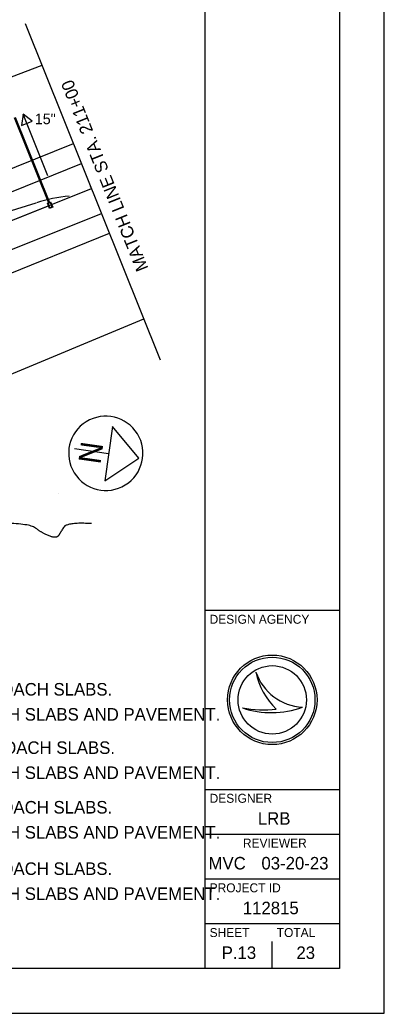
# Model space of a CAD drawing. Extents: x 0 to 3400, y 0 to 2200.
# Drawn here: x 2993 to 3400, y 0 to 1110 of the extents above; entities that cross this region are included whole.
import ezdxf

# ---------------------------------------------------------------- set-up
doc = ezdxf.new("R2010")
doc.units = 0
for name, color, linetype in [('Default', 7, 'Continuous'), ('DR_X_Culvert', 7, 'Continuous'), ('DR_X_Text', 7, 'Continuous'), ('HY_X_Water_Edge', 7, 'Continuous'), ('PV_P_EOP', 7, 'Continuous'), ('RD_X_GR_Rt', 7, 'Continuous'), ('RW_X_Esmt_LA', 7, 'Continuous'), ('SH_Border', 7, 'Continuous'), ('SH_Cut_Line', 7, 'Continuous'), ('SH_Data', 7, 'Continuous')]:
    doc.layers.add(name, color=color, linetype=linetype)

msp = doc.modelspace()

# ---------------------------------------------------------------- linework, layer by layer
at = {"layer": 'Default'}
for p, q in [((2516.4, 697.6), (3073.1, 921.3)), ((3073.1, 921.3), (3072, 924))]:
    msp.add_line(p, q, dxfattribs=at)
for points in [[(3068.5, 919.4), (3073.1, 921.3)], [(2989.6, 887.7), (3063.8, 917.5)]]:
    msp.add_lwpolyline(points, dxfattribs=at)
at = {"layer": 'DR_X_Culvert'}
for p, q in [((3025.2, 904.7), (2986.9, 1000.1)), ((3026.4, 905.2), (2988, 1000.6)), ((3024.5, 904.5), (3027, 905.5)), ((3026.4, 899.8), (3024.5, 904.5)), ((3028.9, 900.8), (3026.4, 899.8)), ((3026.7, 902.6), (3026.7, 902.6)), ((3027, 905.5), (3028.9, 900.8))]:
    msp.add_line(p, q, dxfattribs=at)
msp.add_lwpolyline([(3029.8, 900.4), (3026.1, 898.9), (3023.7, 904.8), (3027.4, 906.3)], close=True, dxfattribs=at)
at = {"layer": 'DR_X_Text'}
for p, q in [((2996.7, 1004.2), (2994.9, 991.6)), ((3006.7, 996.4), (2996.7, 1004.2)), ((3024.4, 935.3), (2996.7, 1004.2)), ((2994.9, 991.8), (3006.7, 996.4))]:
    msp.add_line(p, q, dxfattribs=at)
at = {"layer": 'HY_X_Water_Edge'}
msp.add_open_spline([(3073.2, 546.9), (3045, 548.5), (3038.4, 536.6), (3033.6, 529.9), (3016.3, 537.1), (3006, 546), (2961, 548.1), (2949.8, 543.4), (2942.1, 532.9), (2929.7, 537.6), (2916.8, 538.2), (2902.2, 537.1), (2870.7, 541.7), (2847, 544), (2823.9, 549.5), (2805.1, 567.2), (2793.2, 584.8), (2776.5, 595.7), (2754, 599.6), (2729.9, 599), (2714, 591.1), (2690.6, 580.9), (2666.4, 566.4), (2657.9, 560.2), (2647.7, 559.9), (2638.2, 556.9), (2609.5, 534.6), (2600.4, 523.1), (2582.7, 509.5), (2561.3, 498.8), (2543.4, 486.2)], degree=2, dxfattribs=at)
at = {"layer": 'PV_P_EOP'}
for p, q in [((2787.8, 864.8), (3053, 971.4)), ((2796.8, 842.6), (3061.9, 949.1)), ((2819.2, 786.9), (3084.3, 893.4)), ((2828.1, 764.6), (3093.3, 871.2))]:
    msp.add_line(p, q, dxfattribs=at)
at = {"layer": 'RD_X_GR_Rt'}
msp.add_line((2832.3, 850), (3011.4, 905.4), dxfattribs=at)
msp.add_arc((3060.2, 754.6), 158.5, 94.3743, 107.9297, dxfattribs=at)
at = {"layer": 'RW_X_Esmt_LA'}
for p, q in [((2751.3, 957.9), (3017.8, 1058.9)), ((2947, 698.7), (3131.6, 775.7))]:
    msp.add_line(p, q, dxfattribs=at)
at = {"layer": 'SH_Border'}
for p, q in [((3200, 50), (3200, 2150)), ((3200, 450), (3350, 450)), ((3200, 250), (3350, 250)), ((3200, 200), (3350, 200)), ((3200, 150), (3350, 150)), ((3200, 100), (3350, 100))]:
    msp.add_line(p, q, dxfattribs=at)
msp.add_lwpolyline([(150, 2150), (3350, 2150), (3350, 50), (150, 50)], close=True, dxfattribs=at)
at = {"layer": 'SH_Cut_Line'}
msp.add_line((3073.1, 921.3), (3073.1, 921.3), dxfattribs=at)
msp.add_lwpolyline([(0, 0), (3400, 0), (3400, 2200), (0, 2200)], close=True, dxfattribs=at)
at = {"layer": 'SH_Data'}
for p, q in [((3150.2, 729.3), (2999.2, 1105.3)), ((3096.5, 655.4), (3087.9, 594.5)), ((3126, 620.1), (3096.5, 655.4)), ((3092.2, 624.9), (3053.9, 630.4)), ((3087.9, 594.5), (3126, 620.1)), ((3036.7, 580.9), (3036.7, 580.9)), ((3256.7, 381), (3256.7, 381)), ((3275, 350), (3275, 350)), ((3241.7, 341), (3241.7, 341)), ((3308.7, 341.9), (3308.7, 341.9)), ((3275, 50), (3275, 80)), ((3237.5, 67.5), (3237.5, 67.5))]:
    msp.add_line(p, q, dxfattribs=at)
for radius in [50, 47.7, 47.7, 38.2]:
    msp.add_circle((3275, 350), radius, dxfattribs=at)
for centre, radius, start, end in [((3089, 625.4), 41.5, 31.6982, 31.6817), ((3311.6, 399.8), 58, 198.9257, 198.9319), ((3334.7, 397), 79.6, 191.6379, 191.6421), ((3311.6, 399.8), 58, 198.9319, 267.1657), ((3334.7, 397), 79.6, 191.6421, 226.0947), ((3273.9, 437), 101.3, 251.4576, 290.0832), ((3264.8, 465.4), 126.6, 259.4964, 259.4995), ((3273.9, 437), 101.3, 251.4527, 251.4576), ((3264.8, 465.4), 126.6, 259.4995, 276.6672)]:
    msp.add_arc(centre, radius, start, end, dxfattribs=at)

# ---------------------------------------------------------------- texts
at = {"layer": 'Default'}
for s, p in [('TUS-00077-03.780L (SFN 7902018) - OMIT WORK ON DECK AND APPROACH SLABS. ', (2350.2, 354.8)), ('REPLACE PMAEJ BETWEEN APPROACH SLABS AND PAVEMENT.', (2630.2, 326.8)), ('TUS-00077-03.780R (SFN 7902042) - OMIT WORK ON DECK AND APPROACH SLABS. ', (2350.2, 289.6)), ('REPLACE PMAEJ BETWEEN APPROACH SLABS AND PAVEMENT.', (2630.2, 261.6)), ('TUS-00077-03.880L (SFN 7902077) - OMIT WORK ON DECK AND APPROACH SLABS. ', (2350.2, 223)), ('REPLACE PMAEJ BETWEEN APPROACH SLABS AND PAVEMENT.', (2630.2, 195)), ('TUS-00077-03.880L (SFN 7902107) - OMIT WORK ON DECK AND APPROACH SLABS. ', (2350.2, 154.4)), ('REPLACE PMAEJ BETWEEN APPROACH SLABS AND PAVEMENT.', (2630.2, 126.4))]:
    msp.add_text(s, height=14, dxfattribs=at).set_placement(p)
at = {"layer": 'DR_X_Text'}
msp.add_text('15"', height=11.86, dxfattribs=at).set_placement((3009.8, 993.1))
at = {"layer": 'SH_Data'}
for s, height, rotation, p in [('MATCH LINE STA. 211+00', 14, 111.8893, (3136.8, 832.1)), ('N', 25, 261.9183, (3061.6, 639.8))]:
    msp.add_text(s, height=height, rotation=rotation, dxfattribs=at).set_placement(p)
for s, height, p in [('DESIGN AGENCY', 10, (3205, 435)), ('DESIGNER', 10, (3205, 235)), ('LRB', 14, (3258.9, 210.5)), ('REVIEWER', 10, (3242.2, 185)), ('MVC', 14, (3203.8, 160.5)), ('03-20-23', 14, (3262.9, 160.5)), ('PROJECT ID', 10, (3205, 135)), ('112815', 14, (3242.1, 110.5)), ('SHEET', 10, (3205, 85)), ('TOTAL', 10, (3280, 85)), ('P.13', 14, (3218.5, 60.5)), ('23', 14, (3302, 60.5))]:
    msp.add_text(s, height=height, dxfattribs=at).set_placement(p)

doc.saveas('drawing.dxf')
